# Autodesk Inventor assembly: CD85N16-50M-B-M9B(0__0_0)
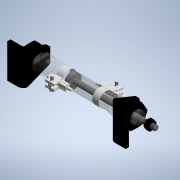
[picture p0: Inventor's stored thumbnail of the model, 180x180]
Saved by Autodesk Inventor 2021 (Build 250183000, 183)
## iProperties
Category: PARTsolutions
Company: SMC
Part Number: CD85N16-50M-B-M9B(0__0_0)
Catalog Web Link: www.cadenas.de
Description: C85/CD85-ISO Standard Air Cylinder:Standard Type Double Acting Single Rod
Vendor: SMC
Document SubType Name: Assembly
Designer: partserver
Manufacturer: SMC
Mass: 43.2798 g
Surface Area: 304.456 cm^2
Volume: 43.2798 cm^3
Density: 1 g/cm^3
PSOL_IDENT_0: {$CADENAS_DATA\23d-libs\smc_jp\actuator\standard_air_cylinder\c85\c85_asmtab.prj},310 {VTYP=3D},{STY
PSOL_IDENT_1: P=ASSTAB},{NB=CD85N16-50M-B-M9B(0__0_0)},{LINA=CD85N16-50M-B-M9B},{NN=C85/CD85},{DATE=09.12.2020 02:
PSOL_IDENT_2: 57:10},{GEOMDATE=01.09.2020 06:51:33},{VERSION=},{LINEID=90},{WBVAR=MAGNET,AUTOSW,LEAD,NUMBER,STROKE
PSOL_IDENT_3: ,POS,CUSHION,BOOT,BRACKET,POSITION,ACCESSORY,SWITCHMT,STOP,OMSC,THREAD},{WBNUMERIC=STROKE,POS}  {NB=
PSOL_IDENT_4: CD85N16-50M-B-M9B(0__0_0)},{LINA=CD85N16-50M-B-M9B},{KT=DUMMY},{ORDER=CD85N16-50M-B-M9B},{BORE=16},{
PSOL_IDENT_5: MOUNT=(N) Basic (Integral clevis)},{MOUNTX=N},{MAGNET=D},{AUTOSW=-M9B},{AUTOSWX='','(-) Without auto
PSOL_IDENT_6: switch','-M9N','M9N','-M9P','M9P','-M9B','M9B','-M9NV','M9NV','-M9PV','M9PV','-M9BV','M9BV','-M9NW'
PSOL_IDENT_7: ,'M9NW','-M9PW','M9PW','-M9BW','M9BW','-M9NWV','M9NWV','-M9PWV','M9PWV','-M9BWV','M9BWV','-M9NA','M9
PSOL_IDENT_8: NA','-M9PA','M9PA','-M9BA','M9BA','-M9NAV','M9NAV','-M9PAV','M9PAV','-M9BAV','M9BAV','-A90','A90','-
PSOL_IDENT_9: A93','A93','-A96','A96','-A90V','A90V','-A93V','A93V','-A96V','A96V','-H7C','H7C','-H7NF','H7NF','-C
PSOL_IDENT_10: 73C','C73C','-C80C','C80C','-J79C','J79C','-F79F','F79F','-A72','A72','-A72H','A72H','-A73C','A73C','
PSOL_IDENT_11: -A80C','A80C','-A79W','A79W'},{LEAD=},{LEADX='','(-) 0.5 m','M','(M) 1 m','L','(L) 3 m','Z','(Z) 5 m'
PSOL_IDENT_12: },{NUMBER=},{NUMBERX='','(-) 2 pcs','S','(S) 1 pc'},{STROKE=50},{STROKEX=[25:40./15.],50,80,100,125,
PSOL_IDENT_13: 160,200},{POS=0},{CUSHION=},{CUSHIONX= '', '(-) Rubber bumper (Standard)', 'C', '(C) Air cushion' },
PSOL_IDENT_14: {BOOT=},{BOOTX= '','N/A' },{BRACKET=M},{BRACKETX='','(-) None','L','(L) Single foot','M','(M) Double
PSOL_IDENT_15: foot','G','(G) Flange','U','(U) Trunnion','N','(N) Clevis'},{POSITION=},{POSITIONX='','N/A'},{ACCES
PSOL_IDENT_16: SORY=},{SWITCHMT=-B},{SWITCHMTX= '-A','(A) Rail mounting','-B','(B) Band mounting' },{STOP=0},{COM=-
PSOL_IDENT_17: },{OMSC=},{OMSCX='','(-) Without order','-XB6','(-XB6) Heat resistant cylinder (–10 to 150°C)','-XC6
PSOL_IDENT_18: A','(-XC6A) Stainless steel used on all standard iron parts','-XC6B','(-XC6B) Stainless steel rod en
PSOL_IDENT_19: d moving parts'},{THREAD=0},{MAX=400},{MAX1=200},{AU=M9A9},{SMIN=15},{SMINN=25},{TIF=NL},{PPATH=c85/
PSOL_IDENT_20: assembly/c85_asmsbl.prj}
NB: CD85N16-50M-B-M9B(0__0_0)
NN: C85/CD85
NT: ISO Standard Air Cylinder:Standard Type Double Acting Single Rod
NBSYN: $ORDER.($POS._$POSITION._$STOP._$THREAD.)
LINA: CD85N16-50M-B-M9B
CATALOG: SMC (JP
BORE: 16
MOUNT: (N) Basic (Integral clevis)
MAGNET: (D) With magnet
AUTOSW: M9B Solid state-General-Grommet-Indicator light:Yes-2 wire-In line
LEAD: (-) 0.5 m
NUMBER: (-) 2 pcs
STROKE: 50
POS: 0
CUSHION: (-) Rubber bumper (Standard)
BOOT: N/A
BRACKET: (M) Double foot
POSITION: N/A
ACCESSORY: (-) None
SWITCHMT: (B) Band mounting
STOP: Standard stroke
COM: -
OMSC: (-) Without order
THREAD: on
SUPPLIER: SMC
ARTICLENO: CD85N16-50M-B-M9B(0__0_0)
BOMINFO: CD85N16-50M-B-M9B
CREATOR: CADENAS GmbH
Title: CD85N16-50M-B-M9B
Author: Cadenas PARTsolutions
Comments: ISO Standard Air Cylinder:Standard Type Double Acting Single Rod
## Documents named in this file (7)
- D:\01 Paralaia\Grupos de Traballo\GT Maquetas\CAD 3D\E_AlimentaciónV1\SMC_JP_CD85N1650MBM9B000\CD85N16-50M-B-M9B(0__0_0).iam
- D:\01 Paralaia\Grupos de Traballo\GT Maquetas\CAD 3D\E_AlimentaciónV1\SMC_JP_CD85N1650MBM9B000\CD85N16-50-B-M9B(0)_BODY.ipt
- D:\01 Paralaia\Grupos de Traballo\GT Maquetas\CAD 3D\E_AlimentaciónV1\SMC_JP_CD85N1650MBM9B000\C8516-50_ROD.ipt
- D:\01 Paralaia\Grupos de Traballo\GT Maquetas\CAD 3D\E_AlimentaciónV1\SMC_JP_CD85N1650MBM9B000\C85NT16(16_).ipt
- D:\01 Paralaia\Grupos de Traballo\GT Maquetas\CAD 3D\E_AlimentaciónV1\SMC_JP_CD85N1650MBM9B000\C85SN16(16_).ipt
- D:\01 Paralaia\Grupos de Traballo\GT Maquetas\CAD 3D\E_AlimentaciónV1\SMC_JP_CD85N1650MBM9B000\D-M9B_C85_(16).ipt
- D:\01 Paralaia\Grupos de Traballo\GT Maquetas\CAD 3D\E_AlimentaciónV1\SMC_JP_CD85N1650MBM9B000\C85L16_16.ipt
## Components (9 placed, 6 different names)
1. CD85N16-50-B-M9B(0)_BODY:1
2. C8516-50_ROD:1
3. C85NT16(16_):1
4. C85SN16(16_):1
5. D-M9B_C85_(16):1
6. D-M9B_C85_(16):2
7. C85L16_16:1
8. C85L16_16:2
9. C85SN16(16_):2
